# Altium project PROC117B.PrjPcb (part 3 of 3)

## Sheet PROC117B_CAN_LIN_PHY_Interface.SchDoc: CAN_LIN_PHY_INTERFACE
size 431 x 279 mm; Date: Not shown in title block; ApprovedBy: Not shown in title block; CheckedBy: Not shown in title block; Author: Not shown in title block; CompanyName: Not shown in title block; DrawnBy: Mistral; Engineer: Not shown in title block; Organization: Not shown in title block; Address1: Not shown in title block; Address2: Not shown in title block; Address3: Not shown in title block; Address4: Not shown in title block; DocumentNumber: 13; Revision: Use project parameter SCH_Rev; SheetNumber: 13; SheetTotal: 16; PageSetup: Record=PageOptions¦CenterHorizontal=True¦CenterVertical=True¦PrintScale=1.00¦XCorrection=1.00¦YCorrection=1.00¦PrintKind=0¦BorderSize=5000000¦LeftOffset=0¦BottomOffset=0¦Orientation=2¦PaperLength=1000¦PaperWidth=1000¦Scale=100¦PaperSource=15¦PrintQuality=600¦MediaType=1¦DitherType=10¦PaperKind=Letter¦PrintScaleMode=1
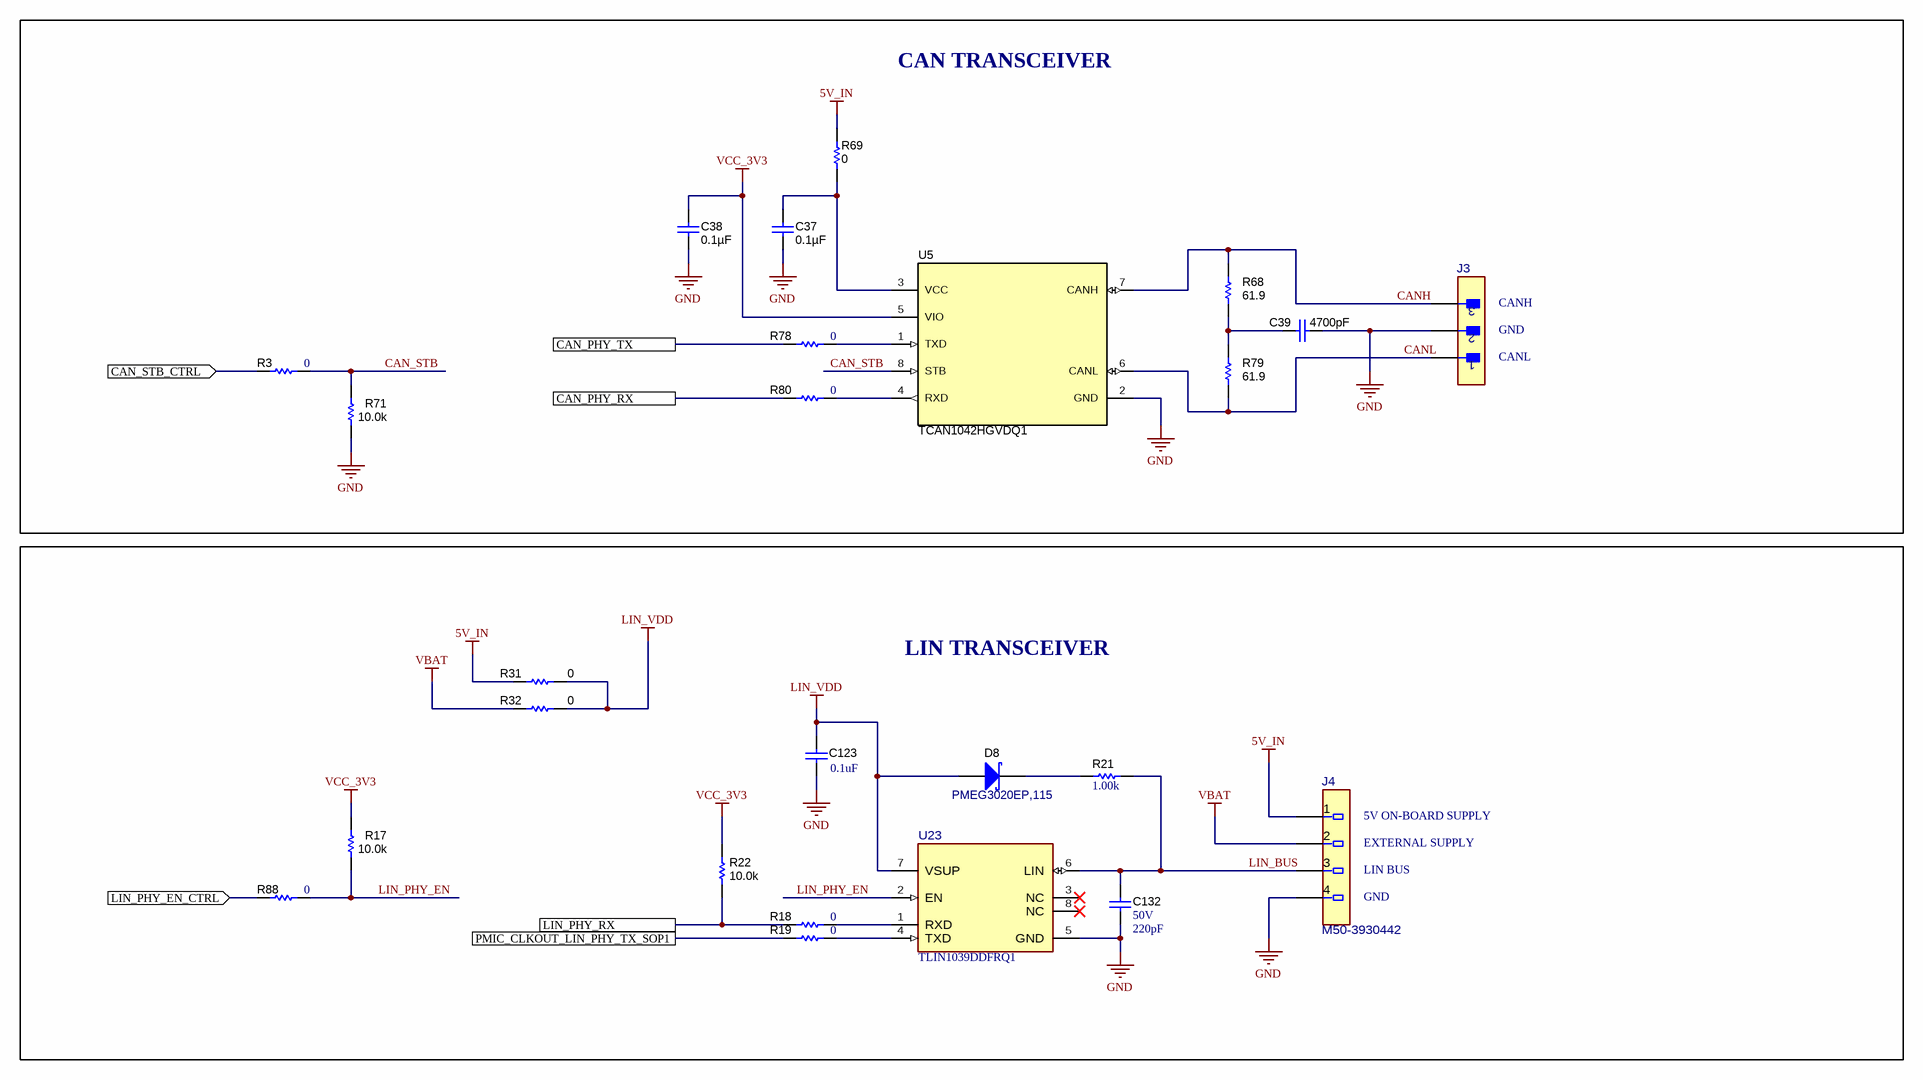
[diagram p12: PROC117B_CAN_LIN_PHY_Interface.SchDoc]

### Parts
C37  ValueDisplayed: 0.1µF  [0402L]  (hidden comment: C0402C104K8RACTU)
C38  ValueDisplayed: 0.1µF  [0402L]  (hidden comment: C0402C104K8RACTU)
C39  ValueDisplayed: 4700pF  [0402L]  (hidden comment: GCM155R71H472KA37D)
C123  ValueDisplayed: 0.1uF  [0402]  (hidden comment: GCM155R71H104KE02D)
C132  VDC_V: 50V  ValueDisplayed: 220pF  [0402]  (hidden comment: 885012005063)
D8  PMEG3020EP,115  [SOD-128]
J3  M50-3930342  [FP-M50-3930342_HDR3-MFG]  (value not drawn)
J4  M50-3930442  [FP-M50-3930442_HDR4-Recommended_Land_Pattern]
R3  ValueDisplayed: 0  [0402]  (hidden comment: ERJ-2GE0R00X)
R17  ValueDisplayed: 10.0k  [0402L]  (hidden comment: CRCW040210K0FKED)
R18  ValueDisplayed: 0  [0402]  (hidden comment: ERJ-2GE0R00X)
R19  ValueDisplayed: 0  [0402]  (hidden comment: ERJ-2GE0R00X)
R21  ValueDisplayed: 1.00k  [0402]  (hidden comment: CRCW04021K00FKED)
R22  ValueDisplayed: 10.0k  [0402L]  (hidden comment: CRCW040210K0FKED)
R31  ValueDisplayed: 0  [0603]  (hidden comment: MCT06030Z0000ZP500)
R32  ValueDisplayed: 0  [0603]  (hidden comment: MCT06030Z0000ZP500)
R68  ValueDisplayed: 61.9  [0402L]  (hidden comment: CRCW040261R9FKED)
R69  ValueDisplayed: 0  [0201_Silk]  (hidden comment: CRCW02010000Z0ED)
R71  ValueDisplayed: 10.0k  [0402L]  (hidden comment: CRCW040210K0FKED)
R78  ValueDisplayed: 0  [0402]  (hidden comment: ERJ-2GE0R00X)
R79  ValueDisplayed: 61.9  [0402L]  (hidden comment: CRCW040261R9FKED)
R80  ValueDisplayed: 0  [0402]  (hidden comment: ERJ-2GE0R00X)
R88  ValueDisplayed: 0  [0402]  (hidden comment: ERJ-2GE0R00X)
U5  TCAN1042HGVDQ1  [D0008A_L]
U23  TLIN1039DDFRQ1  [DDF0008A-MFG]

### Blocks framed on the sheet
CAN TRANSCEIVER: C37-C39 J3 R3 R68 R69 R71 R78-R80 U5
LIN TRANSCEIVER: C123 C132 D8 J4 R17-R19 R21 R22 R31 R32 R88 U23

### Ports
CAN_PHY_RX, CAN_PHY_TX, CAN_STB_CTRL (in), LIN_PHY_EN_CTRL (in), LIN_PHY_RX, PMIC_CLKOUT_LIN_PHY_TX_SOP1

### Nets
5V_IN: J4.1 R31.1 R69.2
GND: C37.1 C38.1 C39.1 C123.2 C132.2 J3.2 J4.4 R71.1 U5.2(GND) U23.5(GND)
LIN_VDD: C123.1 D8.2(A) R31.2 R32.2 U23.7(VSUP)
VBAT: J4.2 R32.1
VCC_3V3: C38.2 R17.2 R22.2 U5.5(VIO)
CAN_PHY_RX: R80.1 ; port CAN_PHY_RX
CAN_PHY_TX: R78.1 ; port CAN_PHY_TX
CAN_STB: R3.2 R71.2 U5.8(STB)
CAN_STB_CTRL: R3.1 ; port CAN_STB_CTRL
CANH: J3.3 R68.2 U5.7(CANH)
CANL: J3.1 R79.1 U5.6(CANL)
LIN_BUS: C132.1 J4.3 R21.1 U23.6(LIN)
LIN_PHY_EN: R17.1 R88.2 U23.2(EN)
LIN_PHY_EN_CTRL: R88.1 ; port LIN_PHY_EN_CTRL
LIN_PHY_RX: R18.1 R22.1 ; port LIN_PHY_RX
PMIC_CLKOUT_LIN_PHY_TX_SOP1: R19.1 ; port PMIC_CLKOUT_LIN_PHY_TX_SOP1
NetC37_2: C37.2 R69.1 U5.3(VCC)
NetC39_2: C39.2 R68.1 R79.2
NetD8_1: D8.1(K) R21.2
NetR18_2: R18.2 U23.1(RXD)
NetR19_2: R19.2 U23.4(TXD)
NetR78_2: R78.2 U5.1(TXD)
NetR80_2: R80.2 U5.4(RXD)

Not connected (* = marked no-connect by the designer): U23 3(NC)* 8(NC)*

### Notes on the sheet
- (near J3) CANH
- (near J3) GND
- (near J3) CANL
- (near J4) EXTERNAL SUPPLY
- (near J4) 5V ON-BOARD SUPPLY
- (near J4) GND
- (near J4) LIN BUS

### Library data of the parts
C37 C38 = CMP-0078241-1: CAP, CERM, 0.1 µF, 10 V,+/- 10%, X7R, 0402; Manufacturer: Kemet; TaMin_C: -55°C; Polarized: N; SizeAreaWB_mm2: 3; U/M: EA; Value: 0.1uF; TaMax_C: 125°C; SizeZ_mm: 0.6; SizeX_mm: 1; SizeY_mm: 0.5; Cap_Case: 0402; Value2: 10V; CompType: Capacitor; Cap_F: 100nF; AEC Category: Q200
C39 = CMP-0006361-2: CAP, CERM, 4700 pF, 50 V, +/- 10%, X7R, AEC-Q200 Grade 1, 0402; Manufacturer: MuRata; TaMin_C: -55°C; Polarized: N; SizeAreaWB_mm2: 3; Value1: Unknown; U/M: EA; Value: 4700pF; TaMax_C: 125°C; SizeZ_mm: 0.6; SizeX_mm: 1; SizeY_mm: 0.5; Cap_Case: 0402; Value2: 50V; AEC Qualified: Y; Cap_F: 4.7nF; AEC Category: Q200
C123 = CMP-0006356-2: CAP, CERM, 0.1 uF, 50 V, +/- 10%, X7R, AEC-Q200 Grade 1, 0402; Manufacturer: MuRata; TaMin_C: -55°C; Polarized: N; SizeAreaWB_mm2: 3; Value1: Unknown; U/M: EA; Value: 0.1uF; TaMax_C: 125°C; SizeZ_mm: 0.6; SizeX_mm: 1; SizeY_mm: 0.5; Value2: 50V; AEC Qualified: Y; Cap_F: 100nF; AEC Category: Q200
C132 = CMP-0006218-2: CAP, CERM, 220 pF, 50 V, +/- 5%, C0G/NP0, 0402; Manufacturer: Wurth Elektronik; TaMin_C: -55°C; Polarized: N; SizeAreaWB_mm2: 3; Value1: Unknown; U/M: EA; Value: 220pF; TaMax_C: 125°C; SizeZ_mm: 0.6; SizeX_mm: 1; SizeY_mm: 0.5; AEC Category: Q200
D8 = CMP-0078758-2: Diode, Schottky, 30 V, 2 A, AEC-Q101, SOD-128; Manufacturer: Nexperia; Value2: 0.36V; SizeAreaWB_mm2: 19.6; Io_A: 2A; Value: 30V; AEC Qualified: Y; TJmax_C: 150°C; SizeX_mm: 4.6; AEC Category: Q101; SizeY_mm: 2.5; SizeArea_mm2: 11.5; Vf_V: 3.6dV; SizeZ_mm: 1.1
J3 = CMP-0087785-1: CONN HEADER R/A 3POS 1.27MM; Manufacturer: Harwin; Row_Count: 1; Current_A: 1A; ContactFinish: Gold,Nickel
J4 = CMP-0087187-1: CONN HDR 1.27MM R/A AU 4POS; Manufacturer: Harwin Inc.; ContactFinish: Gold; Current_A: 1A; Row_Count: 1
R3 R18 R19 R78 R80 R88 = CMP-0026992-3: RES, 0, 5%, 0.1 W, AEC-Q200 Grade 0, 0402; Manufacturer: Panasonic; Power_W: 100mW; TempCo: 600 ppm/C; Value_Code: 0000; Value: 0; EIA_Code: E24; SizeX_mm: 1; SizeY_mm: 0.5; SizeZ_mm: 0.6; Value2: 0.1W; CompType: Resistor; AEC Qualified: Y; VDC_V: 50V; AEC Category: Q200; SizeAreaWB_mm2: 3; INSTALLATION: DNP
R17 R22 R71 = CMP-0025958-3: RES, 10.0 k, 1%, 0.063 W, AEC-Q200 Grade 0, 0402; Manufacturer: Vishay-Dale; Power_W: 63mW; TempCo: 100 ppm/C; Value_Code: 10k0; Value: 10.0k; EIA_Code: E96; Res_ohm: 10k; SizeX_mm: 1; SizeY_mm: 0.5; SizeZ_mm: 0.6; Value2: 0.063W; AEC Qualified: Y; VDC_V: 50V; AEC Category: Q200; AEC Grade: 0
R21 = CMP-0026071-3: RES, 1.00 k, 1%, 0.063 W, AEC-Q200 Grade 0, 0402; Manufacturer: Vishay-Dale; Power_W: 63mW; TempCo: 100 ppm/C; Value_Code: 1k00; Value: 1.00k; EIA_Code: E96; Res_ohm: 1k; SizeX_mm: 1; SizeY_mm: 0.5; SizeZ_mm: 0.6; Value2: 0.063W; AEC Qualified: Y; VDC_V: 50V; AEC Category: Q200; AEC Grade: 0
R31 R32 = CMP-0025884-3: RES, 0, 5%, 0.125 W, 0603; Manufacturer: Vishay/Beyschlag; Power_W: 125mW; TempCo: ppm/C; Value_Code: 0000; U/M: EA; Value: 0; EIA_Code: E24; SizeX_mm: 1.6; SizeY_mm: 0.8; SizeZ_mm: 1; Value2: 0.125W; SizeArea_mm2: 1.28; CompType: Resistor; AEC Qualified: N; AEC Category: Q200; INSTALATION: DNP
R68 R79 = CMP-0026491-2: RES, 61.9, 1%, 0.063 W, AEC-Q200 Grade 0, 0402; Manufacturer: Vishay-Dale; Power_W: 63mW; TempCo: 100 ppm/C; Value_Code: 61R9; Value: 61.9; EIA_Code: E96; SizeX_mm: 1; SizeY_mm: 0.5; SizeZ_mm: 0.6; Value2: 0.063W; AEC Qualified: Y; VDC_V: 50V; AEC Category: Q200; AEC Grade: 0
R69 = CMP-0027008-4: RES, 0, 5%, 0.05 W, 0201; Manufacturer: Vishay-Dale; Power_W: 50mW; TempCo: ppm/C; Value_Code: 0000; Value: 0; EIA_Code: E24; SizeX_mm: 0.6; SizeY_mm: 0.3; SizeZ_mm: 0.26; Value2: 0.05W; SizeArea_mm2: 0.18; AEC Qualified: N; AEC Category: Q200
U5 = CMP-0075992-1: Automotive Fault Protected CAN Transceiver With Flexible Data-Rate, D0008A (SOIC-8); Manufacturer: Texas Instruments; Alternate PartNumber: TCAN1042HGVDRQ1; SizeAreaWB_mm2: 56.58; SizeArea_mm2: 30.38; SizeZ_mm: 1.75; SizeY_mm: 6.2; U/M: EA; CompType: IC; SizeX_mm: 4.9
U23 = CMP-0090433-1: Local Interconnect Network (LIN) Transceiver with Dominant State Timeout; Manufacturer: Texas Instruments; Max Supply Voltage: 36V; SizeZ_mm: 1.1mm; Min Supply Voltage: 4.5V; Standoff Height: 0mm; Nominal Supply Current: 0.3-1.2mA; AEC Grade: Grade 0; TJmax_C: +150°C; Interface: UART,LIN,SCI; AEC Qualified: Yes

## Sheet PROC117B_DCA1000_Connector_Reset.SchDoc: DCA1000_CONN_RESET
size 431 x 279 mm; Date: Not shown in title block; ApprovedBy: Not shown in title block; CheckedBy: Not shown in title block; Author: Not shown in title block; CompanyName: Not shown in title block; DrawnBy: Mistral; Engineer: Not shown in title block; Organization: Not shown in title block; Address1: Not shown in title block; Address2: Not shown in title block; Address3: Not shown in title block; Address4: Not shown in title block; DocumentNumber: 14; Revision: Use project parameter SCH_Rev; SheetNumber: 14; SheetTotal: 16; PageSetup: Record=PageOptions¦CenterHorizontal=True¦CenterVertical=True¦PrintScale=1.00¦XCorrection=1.00¦YCorrection=1.00¦PrintKind=0¦BorderSize=5000000¦LeftOffset=0¦BottomOffset=0¦Orientation=2¦PaperLength=1000¦PaperWidth=1000¦Scale=100¦PaperSource=15¦PrintQuality=600¦MediaType=1¦DitherType=10¦PaperKind=Letter¦PrintScaleMode=1
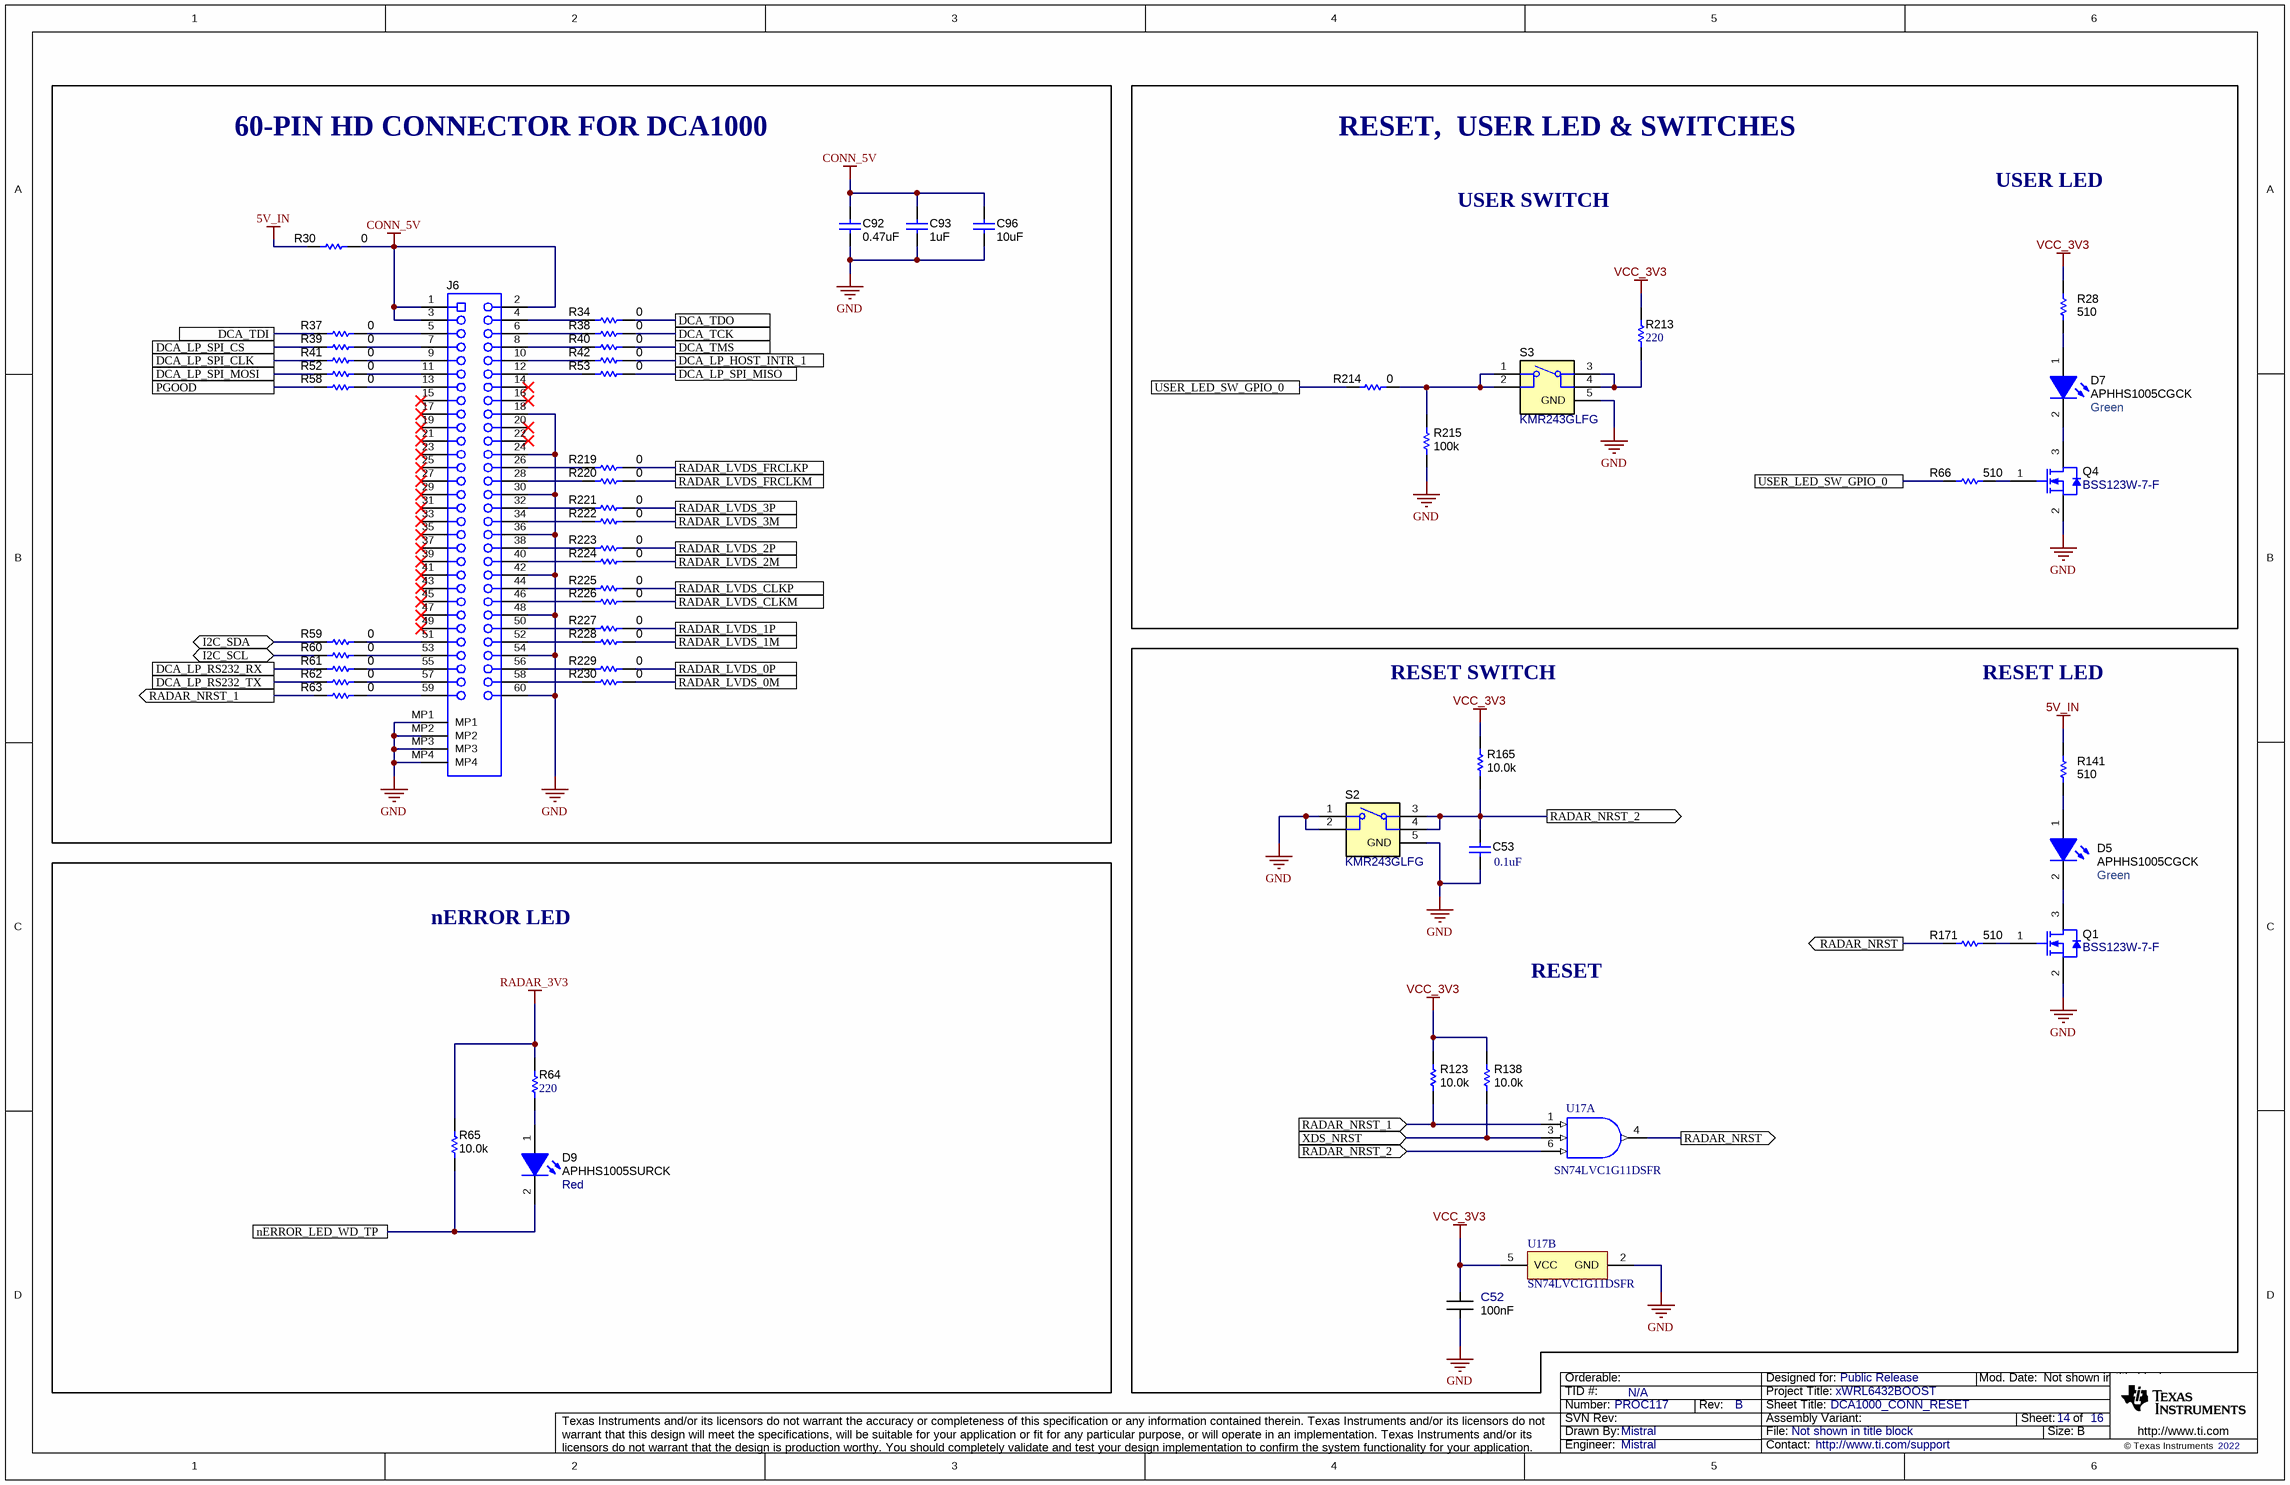
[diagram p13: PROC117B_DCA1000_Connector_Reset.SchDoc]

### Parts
C52  value 100nF  [FP-GRM033R6YA104KE14D_0201 (0603 Metric)-IPC_C]  (hidden comment: GRM033R6YA104KE14D)
C53  ValueDisplayed: 0.1uF  [0402]  (hidden comment: GCM155R71H104KE02D)
C92  ValueDisplayed: 0.47uF  [0402L]  (hidden comment: GCM155C71A474KE36D)
C93  ValueDisplayed: 1uF  [0402L]  (hidden comment: GRT155C81A105KE01D)
C96  ValueDisplayed: 10uF  [0603S]  (hidden comment: GRT188R61A106KE13D)
D5  APHHS1005CGCK  Color: Green  [APHHS1005_Green]
D7  APHHS1005CGCK  Color: Green  [APHHS1005_Green]
D9  APHHS1005SURCK  value Red  [APHHS1005_Red]
J6  QSH-030-01-L-D-A  [Samtec_QSH-030-01-X-D-A]  (value not drawn)
Q1  BSS123W-7-F  [SOT-323]
Q4  BSS123W-7-F  [SOT-323]
R28  value 510  [0201L]  (hidden comment: RC0201JR-07510RL)
R30  ValueDisplayed: 0  [0603]  (hidden comment: MCT06030Z0000ZP500)
R34  ValueDisplayed: 0  [0201_Silk]  (hidden comment: CRCW02010000Z0ED)
R37  ValueDisplayed: 0  [0201_Silk]  (hidden comment: CRCW02010000Z0ED)
R38  ValueDisplayed: 0  [0201_Silk]  (hidden comment: CRCW02010000Z0ED)
R39  ValueDisplayed: 0  [0201_Silk]  (hidden comment: CRCW02010000Z0ED)
R40  ValueDisplayed: 0  [0201_Silk]  (hidden comment: CRCW02010000Z0ED)
R41  ValueDisplayed: 0  [0201_Silk]  (hidden comment: CRCW02010000Z0ED)
R42  ValueDisplayed: 0  [0201_Silk]  (hidden comment: CRCW02010000Z0ED)
R52  ValueDisplayed: 0  [0201_Silk]  (hidden comment: CRCW02010000Z0ED)
R53  ValueDisplayed: 0  [0201_Silk]  (hidden comment: CRCW02010000Z0ED)
R58  ValueDisplayed: 0  [0201_Silk]  (hidden comment: CRCW02010000Z0ED)
R59  ValueDisplayed: 0  [0201_Silk]  (hidden comment: CRCW02010000Z0ED)
R60  ValueDisplayed: 0  [0201_Silk]  (hidden comment: CRCW02010000Z0ED)
R61  ValueDisplayed: 0  [0201_Silk]  (hidden comment: CRCW02010000Z0ED)
R62  ValueDisplayed: 0  [0201_Silk]  (hidden comment: CRCW02010000Z0ED)
R63  ValueDisplayed: 0  [0201_Silk]  (hidden comment: CRCW02010000Z0ED)
R64  ValueDisplayed: 220  [0201]  (hidden comment: RC0201JR-07220RL)
R65  ValueDisplayed: 10.0k  [0402L]  (hidden comment: CRCW040210K0FKED)
R66  value 510  [0201L]  (hidden comment: RC0201JR-07510RL)
R123  ValueDisplayed: 10.0k  [0402L]  (hidden comment: CRCW040210K0FKED)
R138  ValueDisplayed: 10.0k  [0402L]  (hidden comment: CRCW040210K0FKED)
R141  value 510  [0201L]  (hidden comment: RC0201JR-07510RL)
R165  ValueDisplayed: 10.0k  [0402L]  (hidden comment: CRCW040210K0FKED)
R171  value 510  [0201L]  (hidden comment: RC0201JR-07510RL)
R213  ValueDisplayed: 220  [0201]  (hidden comment: RC0201JR-07220RL)
R214  Res_ohm: 0  [FP-RC0201JR-070RL_0201 (0603 Metric)-IPC_C]  (hidden comment: RC0201JR-070RL)
R215  value 100k  [0201L]  (hidden comment: CRCW0201100KFKED)
R219  ValueDisplayed: 0  [0201_Silk]  (hidden comment: CRCW02010000Z0ED)
R220  ValueDisplayed: 0  [0201_Silk]  (hidden comment: CRCW02010000Z0ED)
R221  ValueDisplayed: 0  [0201_Silk]  (hidden comment: CRCW02010000Z0ED)
R222  ValueDisplayed: 0  [0201_Silk]  (hidden comment: CRCW02010000Z0ED)
R223  ValueDisplayed: 0  [0201_Silk]  (hidden comment: CRCW02010000Z0ED)
R224  ValueDisplayed: 0  [0201_Silk]  (hidden comment: CRCW02010000Z0ED)
R225  ValueDisplayed: 0  [0201_Silk]  (hidden comment: CRCW02010000Z0ED)
R226  ValueDisplayed: 0  [0201_Silk]  (hidden comment: CRCW02010000Z0ED)
R227  ValueDisplayed: 0  [0201_Silk]  (hidden comment: CRCW02010000Z0ED)
R228  ValueDisplayed: 0  [0201_Silk]  (hidden comment: CRCW02010000Z0ED)
R229  ValueDisplayed: 0  [0201_Silk]  (hidden comment: CRCW02010000Z0ED)
R230  ValueDisplayed: 0  [0201_Silk]  (hidden comment: CRCW02010000Z0ED)
S2  KMR243GLFG  [SW_KMR243GLFG]
S3  KMR243GLFG  [SW_KMR243GLFG]
U17  SN74LVC1G11DSFR  [DSF0006A]  (parts A,B of 2)

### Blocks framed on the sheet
60-PIN HD CONNECTOR FOR DCA1000: C92 C93 C96 J6 R30 R34 R37-R42 R52 R53 R58-R63 R219-R230
RESET,  USER LED & SWITCHES: D7 Q4 R28 R66 R213-R215 S3
nERROR LED: D9 R64 R65

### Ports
DCA_LP_HOST_INTR_1, DCA_LP_RS232_RX, DCA_LP_RS232_TX, DCA_LP_SPI_CLK, DCA_LP_SPI_CS, DCA_LP_SPI_MISO, DCA_LP_SPI_MOSI, DCA_TCK, DCA_TDI, DCA_TDO, DCA_TMS, I2C_SCL (bidir), I2C_SDA (bidir), nERROR_LED_WD_TP, PGOOD, RADAR_LVDS_0M, RADAR_LVDS_0P, RADAR_LVDS_1M, RADAR_LVDS_1P, RADAR_LVDS_2M, RADAR_LVDS_2P, RADAR_LVDS_3M, RADAR_LVDS_3P, RADAR_LVDS_CLKM, RADAR_LVDS_CLKP, RADAR_LVDS_FRCLKM, RADAR_LVDS_FRCLKP, RADAR_NRST (out), RADAR_NRST_1 (in), RADAR_NRST_1 (out), RADAR_NRST_2 (in), RADAR_NRST_2 (out), USER_LED_SW_GPIO_0, XDS_NRST (in)

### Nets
5V_IN: R30.1 R141.1
CONN_5V: C92.1 C93.1 C96.2 J6.1 J6.2 J6.3 R30.2
GND: C52.1 C53.2 C92.2 C93.2 C96.1 J6.18 J6.24 J6.30 J6.36 J6.42 J6.48 J6.54 J6.60 J6.MP1 J6.MP2 J6.MP3 J6.MP4 Q1.2(S) Q4.2(S) R215.2 S2.1 S2.2 S2.5(GND) S3.5(GND) U17.2(GND)
RADAR_3V3: R64.2 R65.1
VCC_3V3: C52.2 R28.1 R123.2 R138.2 R165.2 R213.2 U17.5(VCC)
DCA_LP_HOST_INTR_1: R42.2 ; port DCA_LP_HOST_INTR_1
DCA_LP_RS232_RX: R61.1 ; port DCA_LP_RS232_RX
DCA_LP_RS232_TX: R62.1 ; port DCA_LP_RS232_TX
DCA_LP_SPI_CLK: R41.1 ; port DCA_LP_SPI_CLK
DCA_LP_SPI_CS: R39.1 ; port DCA_LP_SPI_CS
DCA_LP_SPI_MISO: R53.2 ; port DCA_LP_SPI_MISO
DCA_LP_SPI_MOSI: R52.1 ; port DCA_LP_SPI_MOSI
DCA_TCK: R38.2 ; port DCA_TCK
DCA_TDI: R37.1 ; port DCA_TDI
DCA_TDO: R34.2 ; port DCA_TDO
DCA_TMS: R40.2 ; port DCA_TMS
I2C_SCL: R60.1 ; port I2C_SCL
I2C_SDA: R59.1 ; port I2C_SDA
nERROR_LED_WD_TP: D9.2(K) R65.2 ; port nERROR_LED_WD_TP
PGOOD: R58.1 ; port PGOOD
RADAR_LVDS_0M: R230.2 ; port RADAR_LVDS_0M
RADAR_LVDS_0P: R229.2 ; port RADAR_LVDS_0P
RADAR_LVDS_1M: R228.2 ; port RADAR_LVDS_1M
RADAR_LVDS_1P: R227.2 ; port RADAR_LVDS_1P
RADAR_LVDS_2M: R224.2 ; port RADAR_LVDS_2M
RADAR_LVDS_2P: R223.2 ; port RADAR_LVDS_2P
RADAR_LVDS_3M: R222.2 ; port RADAR_LVDS_3M
RADAR_LVDS_3P: R221.2 ; port RADAR_LVDS_3P
RADAR_LVDS_CLKM: R226.2 ; port RADAR_LVDS_CLKM
RADAR_LVDS_CLKP: R225.2 ; port RADAR_LVDS_CLKP
RADAR_LVDS_FRCLKM: R220.2 ; port RADAR_LVDS_FRCLKM
RADAR_LVDS_FRCLKP: R219.2 ; port RADAR_LVDS_FRCLKP
RADAR_NRST: R171.1 U17.4(Y) ; port RADAR_NRST
RADAR_NRST_1: R63.1 R123.1 U17.1(A) ; port RADAR_NRST_1
RADAR_NRST_2: C53.1 R165.1 S2.3 S2.4 U17.6(C) ; port RADAR_NRST_2
USER_LED_SW_GPIO_0: R66.1 R214.2 ; port USER_LED_SW_GPIO_0
XDS_NRST: R138.1 U17.3(B) ; port XDS_NRST
NetD5_1: D5.1(A) R141.2
NetD5_2: D5.2(K) Q1.3(D)
NetD7_1: D7.1(A) R28.2
NetD7_2: D7.2(K) Q4.3(D)
NetD9_1: D9.1(A) R64.1
NetJ6_4: J6.4 R34.1
NetJ6_5: J6.5 R37.2
NetJ6_6: J6.6 R38.1
NetJ6_7: J6.7 R39.2
NetJ6_8: J6.8 R40.1
NetJ6_9: J6.9 R41.2
NetJ6_10: J6.10 R42.1
NetJ6_11: J6.11 R52.2
NetJ6_12: J6.12 R53.1
NetJ6_13: J6.13 R58.2
NetJ6_26: J6.26 R219.1
NetJ6_28: J6.28 R220.1
NetJ6_32: J6.32 R221.1
NetJ6_34: J6.34 R222.1
NetJ6_38: J6.38 R223.1
NetJ6_40: J6.40 R224.1
NetJ6_44: J6.44 R225.1
NetJ6_46: J6.46 R226.1
NetJ6_50: J6.50 R227.1
NetJ6_51: J6.51 R59.2
NetJ6_52: J6.52 R228.1
NetJ6_53: J6.53 R60.2
NetJ6_55: J6.55 R61.2
NetJ6_56: J6.56 R229.1
NetJ6_57: J6.57 R62.2
NetJ6_58: J6.58 R230.1
NetJ6_59: J6.59 R63.2
NetQ1_1: Q1.1(G) R171.2
NetQ4_1: Q4.1(G) R66.2
NetR213_1: R213.1 S3.3 S3.4
NetR214_1: R214.1 R215.1 S3.1 S3.2

Not connected (* = marked no-connect by the designer): J6 14* 15* 16* 17* 19* 20* 21* 22* 23* 25* 27* 29* 31* 33* 35* 37* 39* 41* 43* 45* 47* 49*

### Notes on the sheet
- USER SWITCH
- USER LED
- RESET SWITCH
- RESET LED
- RESET

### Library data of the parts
C52 = CMP-0086440-1: Cap Ceramic 0.1uF 35V X5R 10% Pad SMD 0201 85C T/R; Manufacturer: Murata Electronics North America; AEC Qualified: No; SizeZ_mm: 0.33mm; Symbol Name: SYM-GRM033R6YA104KE14D; TempCo: 15%
C53 = CMP-0006356-2: as C123 on sheet PROC117B_CAN_LIN_PHY_Interface
C92 = CMP-0064967-2: CAP, CERM, 0.47 uF, 10 V,+/- 10%, X7S, 0402; Manufacturer: MuRata; Polarized: N; Value: 0.47uF; U/M: EA; Cap_F: 470nF; Value1: Unknown; VDC_V: 10V; TaMin_C: -55°C; TaMax_C: 125°C; Cap_Case: 0402; SizeArea_mm2: 0.5; SizeAreaWB_mm2: 3; SizeX_mm: 1; SizeZ_mm: 0.6; AEC Category: Q200
C93 = CMP-0006272-2: CAP, CERM, 1 uF, 10 V, +/- 10%, X6S, 0402; Manufacturer: TDK; Polarized: N; Value: 1uF; U/M: EA; Cap_F: 1µF; Value1: Unknown; VDC_V: 16V; TempCo: X5R; TaMin_C: -55°C; TaMax_C: 85°C; Cap_Case: 0402; SizeArea_mm2: 0.5; SizeAreaWB_mm2: 3; SizeX_mm: 1; SizeZ_mm: 0.6; AEC Category: Q200
C96 = CMP-0007497-5: CAP, CERM, 10 uF, 10 V, +/- 10%, X5R, 0603; Manufacturer: MuRata; Polarized: N; Value: 10uF; U/M: EA; Cap_F: 10µF; Tolerance_%: 20%; Value1: Unknown; VDC_V: 10V; TempCo: X7R; TaMin_C: -55°C; TaMax_C: 125°C; Cap_Case: 0603; SizeArea_mm2: 1.28; SizeAreaWB_mm2: 4.68; SizeX_mm: 1.6; SizeY_mm: 0.8; SizeZ_mm: 1; AEC Category: Q200
D5 D7 = CMP-0067682-2: LED, Green, SMD; Manufacturer: Kingbright; Angle: 120.0; Power_TotalModule: 75mW; SizeZ_mm: 0.6; Vf_V: 2.1V; Vr_V: 5V; Io_A: 20mA; Ir_A: 10µA; SizeArea_mm2: 0.5; SizeAreaWB_mm2: 3.0; SizeX_mm: 1.0; Tjmax_C: 85°C; Value1: 0.075W
D9 = CMP-0067681-2: LED, Red, SMD; Manufacturer: Kingbright; Vf_V: 1.95V; SizeAreaWB_mm2: 3.0; Tjmax_C: 85°C; SizeX_mm: 1.0; Io_A: 20mA; SizeArea_mm2: 0.5; Vr_V: 5V; Value1: 0.075W; SizeZ_mm: 0.6; Angle: 120.0; Ir_A: 10µA; Power_TotalModule: 75mW
J6 = CMP-0075524-1: Receptacle, 0.5 mm, 30x2, Gold, TH; Manufacturer: Samtec; Pitch_mm: 0.5; Gender: Female; Green_REACh: Passed; CT: False; Shrouded: N; RowSpacing_mm: 5.73; Green_Lifecycle: Active; Row_Count: 2
Q1 Q4 = CMP-0000948-2: MOSFET, N-CH, 100 V, 0.17 A, SOT-323; Alternate Manufacturer: None; Manufacturer: Diodes Inc.; SizeZ_mm: 1.1; ChType: N; Value1: 1; VdsMax_V: 100V; SizeX_mm: 2.2; Vgs_V: 20V; Value: 100V; Rdson45_ohm: 10; SizeArea_mm2: 4.84; AEC Category: Q101; IdsMax_A: 1.7dA; SizeAreaWB_mm2: 10.24; U/M: EA
R28 R66 R141 R171 = CMP-0027137-1: RES, 510, 5%, 0.05 W, 0201; Manufacturer: Yageo America; AEC Category: Q200; AEC Qualified: N; EIA_Code: E24; Power_W: 50mW; SizeArea_mm2: 0.18; SizeX_mm: 0.6; SizeY_mm: 0.3; SizeZ_mm: 0.26; TempCo: 200 ppm/C; U/M: EA; Value2: 0.05W; Value_Code: 510R; VDC_V: 25V
R30 = CMP-0025884-3: as R31 on sheet PROC117B_CAN_LIN_PHY_Interface
R34 R37-R42 R52 R53 R58-R63 R219-R230 = CMP-0027008-4: as R69 on sheet PROC117B_CAN_LIN_PHY_Interface
R64 R213 = CMP-0027072-1: RES, 220, 5%, 0.05 W, 0201; Manufacturer: Yageo America; Power_W: 50mW; TempCo: 200 ppm/C; Value_Code: 220R; U/M: EA; Value: 220; EIA_Code: E24; SizeX_mm: 0.6; SizeY_mm: 0.3; SizeZ_mm: 0.26; Value2: 0.05W; SizeArea_mm2: 0.18; AEC Qualified: N; VDC_V: 25V; AEC Category: Q200
R65 R123 R138 R165 = CMP-0025958-3: as R17 on sheet PROC117B_CAN_LIN_PHY_Interface
R214 = CMP-0086442-2: RES SMD 0 OHM JUMPER 1/20W 0201; Manufacturer: Yageo; AEC Qualified: No; Power_W: 50mW; SizeZ_mm: 0.26mm; TempCo: 200ppm/°C; Tolerance_%: 5%; VDC_V: 25V
R215 = CMP-0027261-3: RES, 100 k, 1%, 0.05 W, 0201; Manufacturer: Vishay-Dale; AEC Category: Q200; AEC Qualified: N; EIA_Code: E96; Power_W: 50mW; SizeArea_mm2: 0.18; SizeX_mm: 0.6; SizeY_mm: 0.3; SizeZ_mm: 0.26; TempCo: 100 ppm/C; Value2: 0.05W; VDC_V: 30V
S2 S3 = CMP-0002325-1: Switch, SPST-NO, Off-Mom, 0.01 A, 32 VDC, SMD; Manufacturer: C&K Components; CurrentRating_mA: 10A; PositionCount: 1; SizeX_mm: 4.6; SizeY_mm: 2.8; SizeZ_mm: 1.9; SizeArea_mm2: 12.88; VDC_V: 32V; SizeAreaWB_mm2: 21.28
U17 = CMP-0051215-4: Single 3-Input Positive-AND Gate, DSF0006A, LARGE T&R; Manufacturer: Texas Instruments; Output Type: CMOS; Bits(#): 1; Input Type: CMOS/TTL; Technology Family: LVC; Schmitt Trigger: No; VCC(Max)(V): 5.5; Gate Type: AND; Rating: Catalog; Output Drive (IOL/IOH)(Max)(mA): 32/-32; ICC @ Nom Voltage(Max)(mA): 0.01; VCC(Min)(V): 1.65; F @ Nom Voltage(Max)(Mhz): 150; Logic: True; Voltage(Nom)(V): 1.8,2.5,3.3,5; tpd @ Nom Voltage(Max)(ns): 20,7.8,6.2,4.6

## Sheet PROC117B_LP_BP_Connector.SchDoc: LP_BP_CONN_HEADER
size 431 x 279 mm; Date: Not shown in title block; ApprovedBy: Not shown in title block; CheckedBy: Not shown in title block; Author: Not shown in title block; CompanyName: Not shown in title block; DrawnBy: Mistral; Engineer: Not shown in title block; Organization: Not shown in title block; Address1: Not shown in title block; Address2: Not shown in title block; Address3: Not shown in title block; Address4: Not shown in title block; DocumentNumber: 15; Revision: Use project parameter SCH_Rev; SheetNumber: 15; SheetTotal: 16; PageSetup: Record=PageOptions¦CenterHorizontal=True¦CenterVertical=True¦PrintScale=1.00¦XCorrection=1.00¦YCorrection=1.00¦PrintKind=0¦BorderSize=5000000¦LeftOffset=0¦BottomOffset=0¦Orientation=2¦PaperLength=1000¦PaperWidth=1000¦Scale=100¦PaperSource=15¦PrintQuality=600¦MediaType=1¦DitherType=10¦PaperKind=Letter¦PrintScaleMode=1
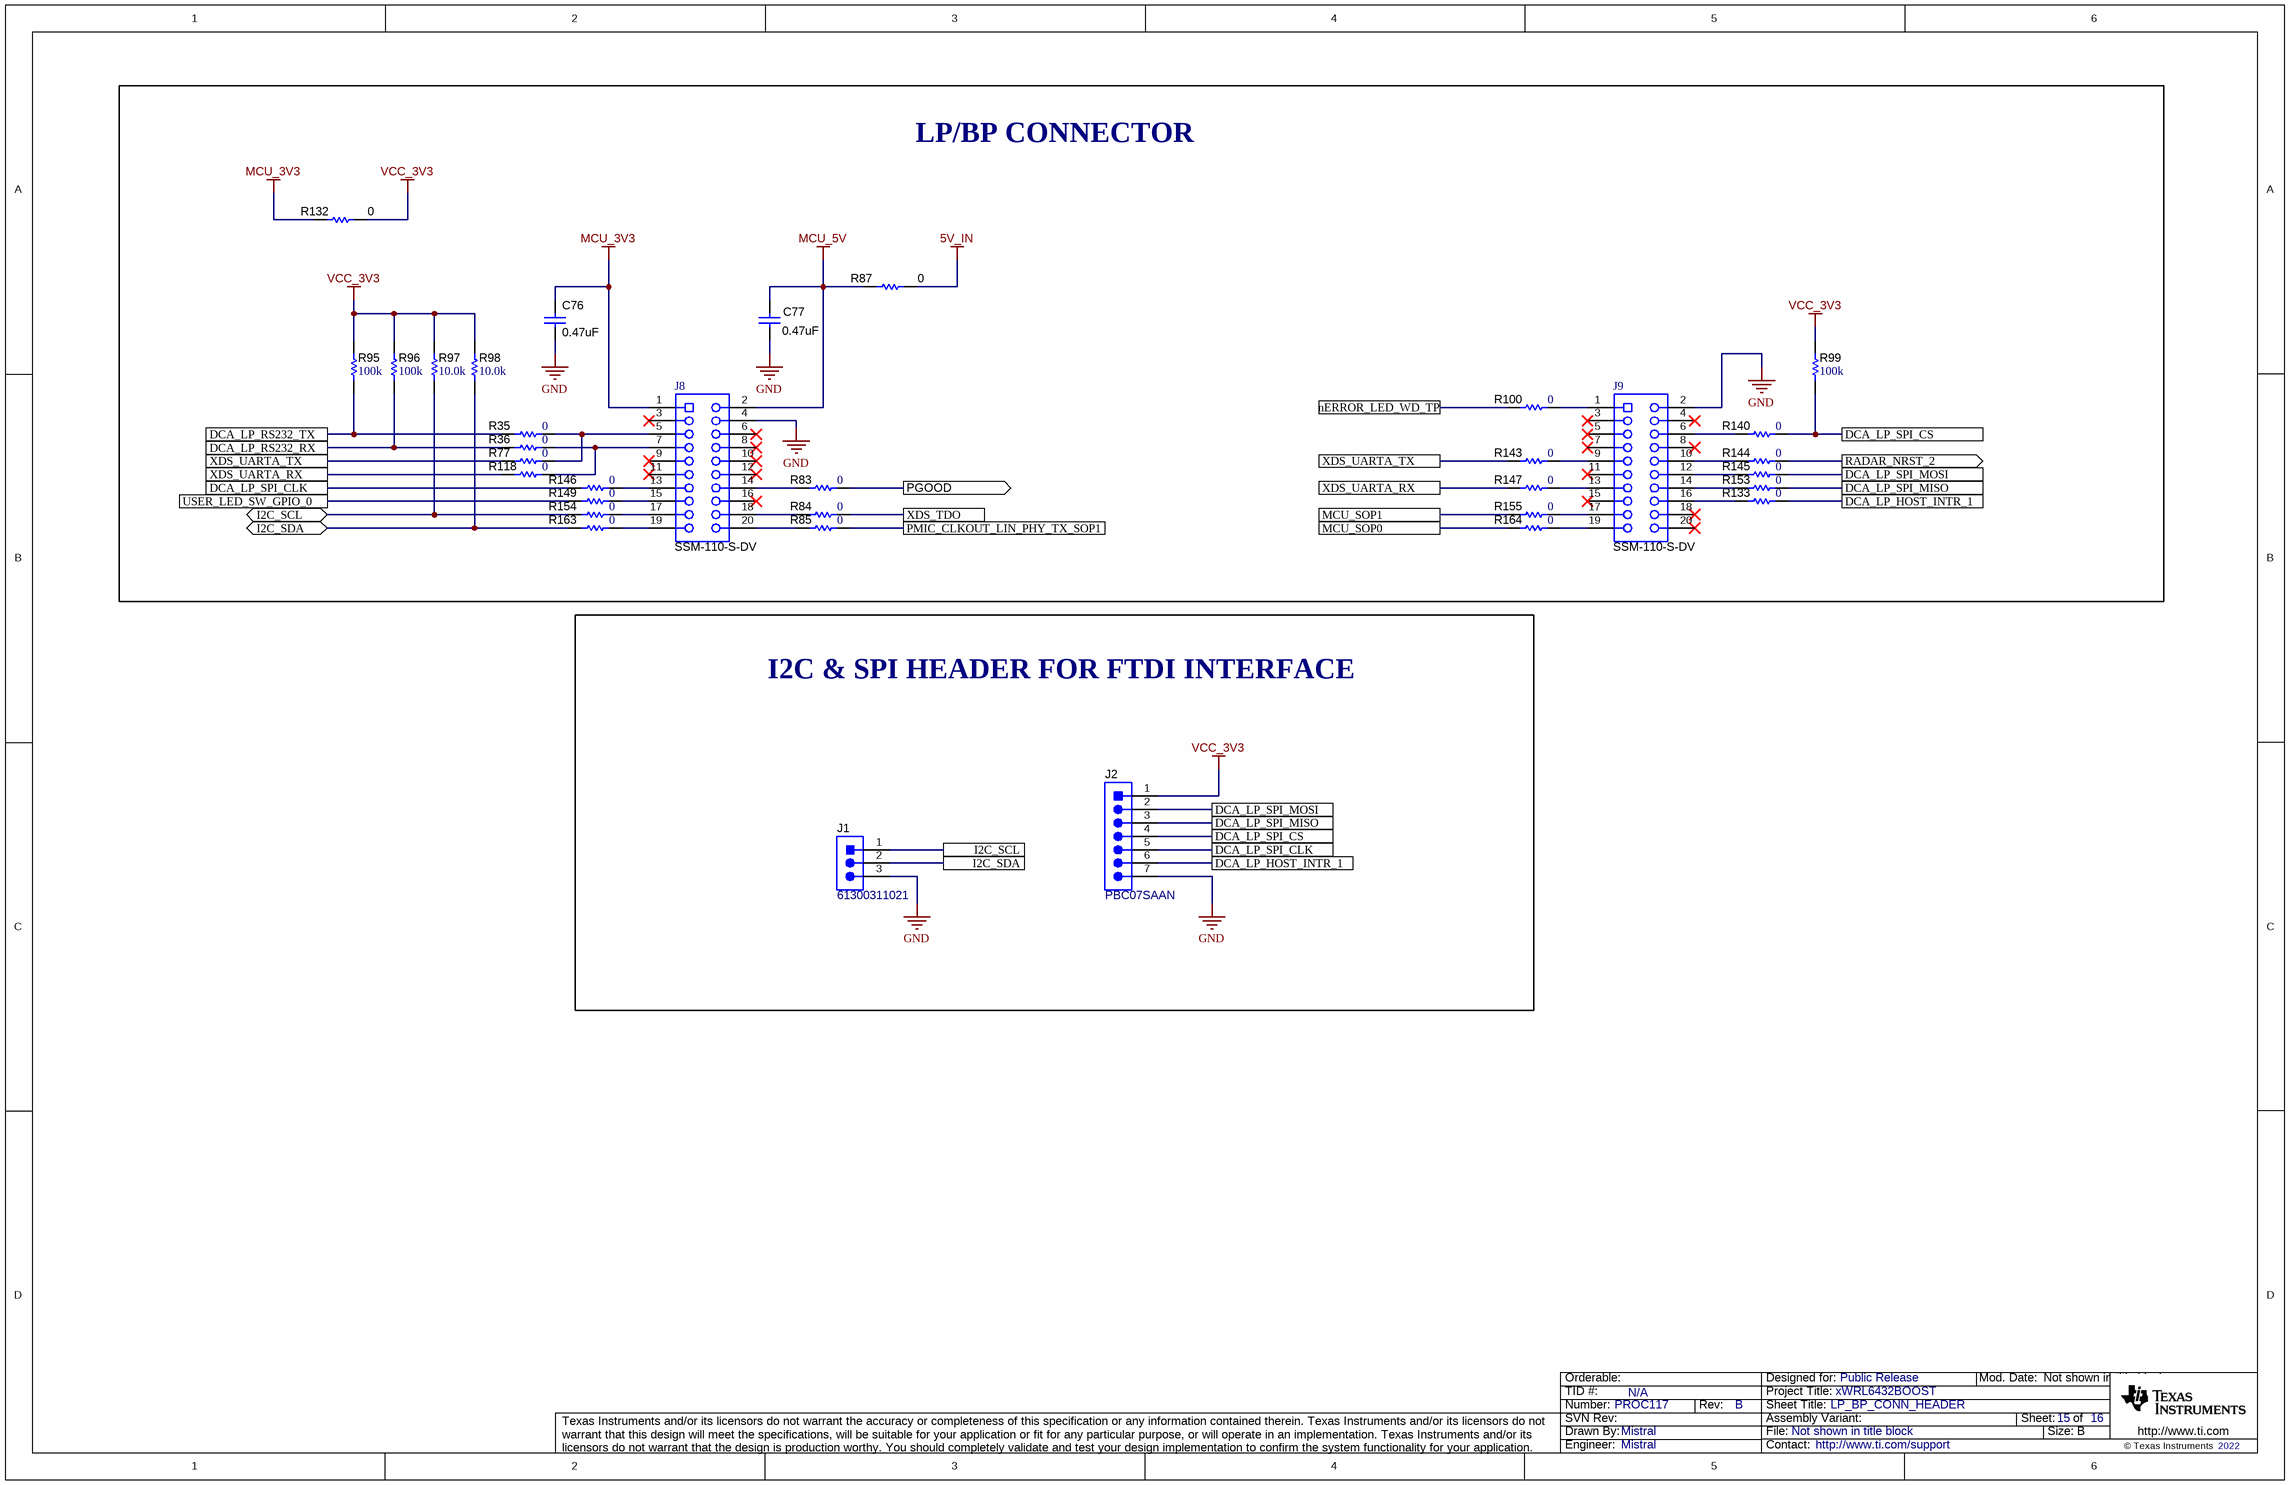
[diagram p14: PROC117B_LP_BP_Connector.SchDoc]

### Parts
C76  ValueDisplayed: 0.47uF  [0402L]  (hidden comment: GCM155C71A474KE36D)
C77  ValueDisplayed: 0.47uF  [0402L]  (hidden comment: GCM155C71A474KE36D)
J1  61300311021  [Wurth_61300311021]
J2  PBC07SAAN  [Sullins_xxC07SAAN]
J8  SSM-110-S-DV  [Samtec_SSM-110-x-DV]
J9  SSM-110-S-DV  [Samtec_SSM-110-x-DV]
R35  ValueDisplayed: 0  [0201_Silk]  (hidden comment: CRCW02010000Z0ED)
R36  ValueDisplayed: 0  [0201_Silk]  (hidden comment: CRCW02010000Z0ED)
R77  ValueDisplayed: 0  [0201_Silk]  (hidden comment: CRCW02010000Z0ED)
R83  ValueDisplayed: 0  [0201_Silk]  (hidden comment: CRCW02010000Z0ED)
R84  ValueDisplayed: 0  [0201_Silk]  (hidden comment: CRCW02010000Z0ED)
R85  ValueDisplayed: 0  [0201_Silk]  (hidden comment: CRCW02010000Z0ED)
R87  ValueDisplayed: 0  [0603]  (hidden comment: MCT06030Z0000ZP500)
R95  ValueDisplayed: 100k  [0402L]  (hidden comment: CRCW0402100KFKED)
R96  ValueDisplayed: 100k  [0402L]  (hidden comment: CRCW0402100KFKED)
R97  ValueDisplayed: 10.0k  [0402L]  (hidden comment: CRCW040210K0FKED)
R98  ValueDisplayed: 10.0k  [0402L]  (hidden comment: CRCW040210K0FKED)
R99  ValueDisplayed: 100k  [0402L]  (hidden comment: CRCW0402100KFKED)
R100  ValueDisplayed: 0  [0201_Silk]  (hidden comment: CRCW02010000Z0ED)
R118  ValueDisplayed: 0  [0201_Silk]  (hidden comment: CRCW02010000Z0ED)
R132  ValueDisplayed: 0  [0603]  (hidden comment: MCT06030Z0000ZP500)
R133  ValueDisplayed: 0  [0201_Silk]  (hidden comment: CRCW02010000Z0ED)
R140  ValueDisplayed: 0  [0201_Silk]  (hidden comment: CRCW02010000Z0ED)
R143  ValueDisplayed: 0  [0201_Silk]  (hidden comment: CRCW02010000Z0ED)
R144  ValueDisplayed: 0  [0201_Silk]  (hidden comment: CRCW02010000Z0ED)
R145  ValueDisplayed: 0  [0201_Silk]  (hidden comment: CRCW02010000Z0ED)
R146  ValueDisplayed: 0  [0201_Silk]  (hidden comment: CRCW02010000Z0ED)
R147  ValueDisplayed: 0  [0201_Silk]  (hidden comment: CRCW02010000Z0ED)
R149  ValueDisplayed: 0  [0201_Silk]  (hidden comment: CRCW02010000Z0ED)
R153  ValueDisplayed: 0  [0201_Silk]  (hidden comment: CRCW02010000Z0ED)
R154  ValueDisplayed: 0  [0201_Silk]  (hidden comment: CRCW02010000Z0ED)
R155  ValueDisplayed: 0  [0201_Silk]  (hidden comment: CRCW02010000Z0ED)
R163  ValueDisplayed: 0  [0201_Silk]  (hidden comment: CRCW02010000Z0ED)
R164  ValueDisplayed: 0  [0201_Silk]  (hidden comment: CRCW02010000Z0ED)

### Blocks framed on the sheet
LP/BP CONNECTOR: C76 C77 J8 J9 R35 R36 R77 R83-R85 R87 R95-R100 R118 R132 R133 R140 R143-R147 R149 R153-R155 R163 R164
I2C & SPI HEADER FOR FTDI INTERFACE: J1 J2

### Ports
DCA_LP_HOST_INTR_1, DCA_LP_RS232_RX, DCA_LP_RS232_TX, DCA_LP_SPI_CLK, DCA_LP_SPI_CS, DCA_LP_SPI_MISO, DCA_LP_SPI_MOSI, I2C_SCL, I2C_SCL (bidir), I2C_SDA, I2C_SDA (bidir), MCU_SOP0, MCU_SOP1, nERROR_LED_WD_TP, PGOOD (out), PMIC_CLKOUT_LIN_PHY_TX_SOP1, RADAR_NRST_2 (out), USER_LED_SW_GPIO_0, XDS_TDO, XDS_UARTA_RX, XDS_UARTA_TX

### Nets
5V_IN: R87.2
GND: C76.2 C77.2 J1.3 J2.7 J8.4 J9.2
MCU_3V3: C76.1 J8.1 R132.1
MCU_5V: C77.1 J8.2 R87.1
VCC_3V3: J2.1 R95.2 R96.2 R97.2 R98.2 R99.2 R132.2
DCA_LP_HOST_INTR_1: J2.6 R133.2 ; port DCA_LP_HOST_INTR_1
DCA_LP_RS232_RX: R36.1 R96.1 ; port DCA_LP_RS232_RX
DCA_LP_RS232_TX: R35.1 R95.1 ; port DCA_LP_RS232_TX
DCA_LP_SPI_CLK: J2.5 R146.1 ; port DCA_LP_SPI_CLK
DCA_LP_SPI_CS: J2.4 R99.1 R140.2 ; port DCA_LP_SPI_CS
DCA_LP_SPI_MISO: J2.3 R153.2 ; port DCA_LP_SPI_MISO
DCA_LP_SPI_MOSI: J2.2 R145.2 ; port DCA_LP_SPI_MOSI
I2C_SCL: J1.1 R97.1 R154.1 ; port I2C_SCL
I2C_SDA: J1.2 R98.1 R163.1 ; port I2C_SDA
MCU_SOP0: R164.1 ; port MCU_SOP0
MCU_SOP1: R155.1 ; port MCU_SOP1
nERROR_LED_WD_TP: R100.1 ; port nERROR_LED_WD_TP
PGOOD: R83.2 ; port PGOOD
PMIC_CLKOUT_LIN_PHY_TX_SOP1: R85.2 ; port PMIC_CLKOUT_LIN_PHY_TX_SOP1
RADAR_NRST_2: R144.2 ; port RADAR_NRST_2
USER_LED_SW_GPIO_0: R149.1 ; port USER_LED_SW_GPIO_0
XDS_TDO: R84.2 ; port XDS_TDO
XDS_UARTA_RX: R118.1 R147.1 ; port XDS_UARTA_RX
XDS_UARTA_TX: R77.1 R143.1 ; port XDS_UARTA_TX
NetJ8_5: J8.5 R35.2 R77.2
NetJ8_7: J8.7 R36.2 R118.2
NetJ8_13: J8.13 R146.2
NetJ8_14: J8.14 R83.1
NetJ8_15: J8.15 R149.2
NetJ8_17: J8.17 R154.2
NetJ8_18: J8.18 R84.1
NetJ8_19: J8.19 R163.2
NetJ8_20: J8.20 R85.1
NetJ9_1: J9.1 R100.2
NetJ9_6: J9.6 R140.1
NetJ9_9: J9.9 R143.2
NetJ9_10: J9.10 R144.1
NetJ9_12: J9.12 R145.1
NetJ9_13: J9.13 R147.2
NetJ9_14: J9.14 R153.1
NetJ9_16: J9.16 R133.1
NetJ9_17: J9.17 R155.2
NetJ9_19: J9.19 R164.2

Not connected (* = marked no-connect by the designer): J8 3* 6* 8* 9* 10* 11* 12* 16*; J9 3* 4* 5* 7* 8* 11* 15* 18* 20*

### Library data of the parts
C76 C77 = CMP-0064967-2: as C92 on sheet PROC117B_DCA1000_Connector_Reset
J1 = CMP-0054795-1: Header, 2.54 mm, 3x1, Gold, R/A, TH; Manufacturer: Wurth Elektronik; CNHeader: TRUE; Shrouded: N; Gender: Male; Row_Count: 1; Pitch_mm: 2.54; CT: FALSE
J2 = CMP-0054584-1: Header, 2.54 mm, 7x1, Gold, TH; Manufacturer: Sullins Connector Solutions; CNHeader: TRUE; Current_A: 3A; Shrouded: N; Gender: Male; Voltage_V: 1.8kV; Row_Count: 1; Pitch_mm: 2.54; CT: FALSE; Cert_UL: Y
J8 J9 = CMP-0078182-1: Receptacle, 2.54mm, 10x2, Gold with Tin tail, SMT; Manufacturer: Samtec; Pitch_mm: 2.54; Gender: Female; Cert_CSA: Y; Voltage_V: 405V; Current_A: 5.2A; Row_Count: 2; CompType: Socket Strip
R35 R36 R77 R83-R85 R100 R118 R133 R140 R143-R147 R149 R153-R155 R163 R164 = CMP-0027008-4: as R69 on sheet PROC117B_CAN_LIN_PHY_Interface
R87 R132 = CMP-0025884-3: as R31 on sheet PROC117B_CAN_LIN_PHY_Interface
R95 R96 R99 = CMP-0025950-3: RES, 100 k, 1%, 0.063 W, AEC-Q200 Grade 0, 0402; Manufacturer: Vishay-Dale; Power_W: 63mW; TempCo: 100 ppm/C; Value: 100k; EIA_Code: E96; SizeX_mm: 1; SizeY_mm: 0.5; SizeZ_mm: 0.6; Value2: 0.063W; AEC Qualified: Y; VDC_V: 50V; AEC Category: Q200; AEC Grade: 0
R97 R98 = CMP-0025958-3: as R17 on sheet PROC117B_CAN_LIN_PHY_Interface

## Sheet PROC117B_EVM_Hardware.SchDoc: HARDWARE
size 431 x 279 mm; Date: Not shown in title block; ApprovedBy: Not shown in title block; CheckedBy: Not shown in title block; Author: Not shown in title block; CompanyName: Not shown in title block; DrawnBy: Mistral; Engineer: Not shown in title block; Organization: Not shown in title block; Address1: Not shown in title block; Address2: Not shown in title block; Address3: Not shown in title block; Address4: Not shown in title block; DocumentNumber: 16; Revision: Use project parameter SCH_Rev; SheetNumber: 16; SheetTotal: 16; PageSetup: Record=PageOptions¦CenterHorizontal=True¦CenterVertical=True¦PrintScale=1.00¦XCorrection=1.00¦YCorrection=1.00¦PrintKind=0¦BorderSize=5000000¦LeftOffset=0¦BottomOffset=0¦Orientation=2¦PaperLength=1000¦PaperWidth=1000¦Scale=100¦PaperSource=15¦PrintQuality=600¦MediaType=1¦DitherType=10¦PaperKind=Letter¦PrintScaleMode=1
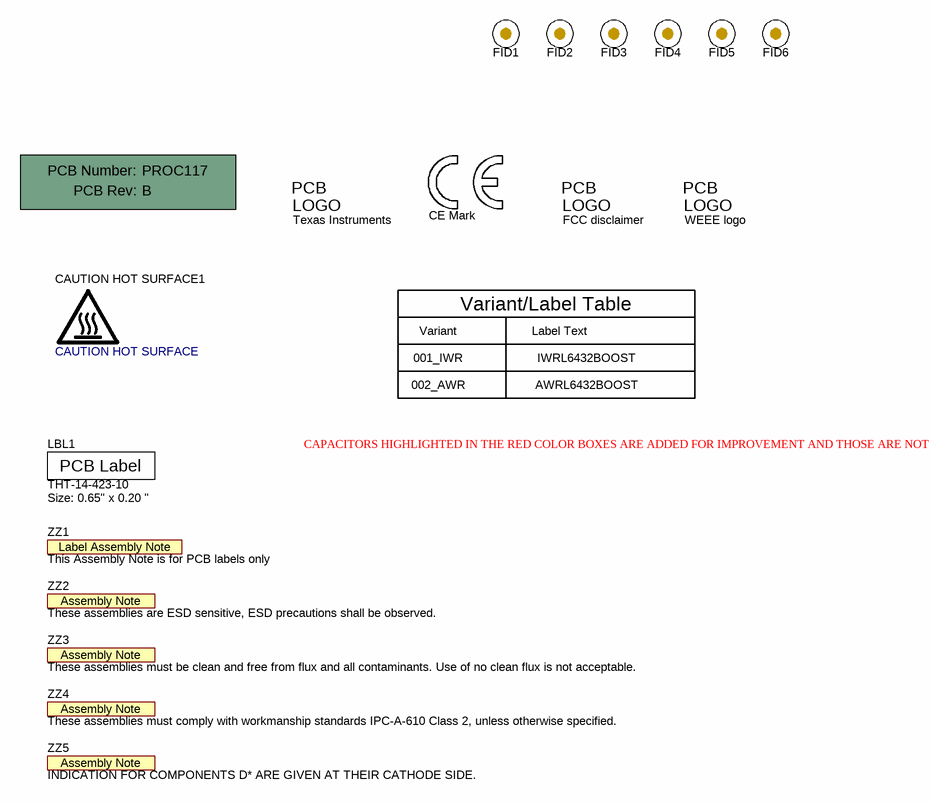
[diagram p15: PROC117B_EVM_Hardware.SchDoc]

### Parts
!PCB  Printed Circuit Board  (value not drawn)  (mechanical)
CAUTION_HOT_SURFACE1  CAUTION HOT SURFACE  [IEC_HotSurface_Small]  (no BOM)
FID1  Fiducial  [Fiducial10-20]  (value not drawn)
FID2  Fiducial  [Fiducial10-20]  (value not drawn)
FID3  Fiducial  [Fiducial10-20]  (value not drawn)
FID4  Fiducial  [Fiducial10-20]  (value not drawn)
FID5  Fiducial  [Fiducial10-20]  (value not drawn)
FID6  Fiducial  [Fiducial10-20]  (value not drawn)
LBL1  THT-14-423-10  Note: Size: 0.65" x 0.20 "  [Label_650x200]
Logo1  Texas Instruments  [TI_Stacked_Overlay_Small]  (no BOM)
Logo2  CE Mark  [CE_Mark_5mm]  (no BOM)
Logo3  FCC disclaimer  [FCC_disclaimer]  (no BOM)
Logo4  WEEE logo  [WEEE_Minimum]  (no BOM)
ZZ1  This Assembly Note is for PCB labels only  [AssemblyNoteLabel]  (no BOM)
ZZ2  These assemblies are ESD sensitive, ESD precautions shall be observed.  [AssemblyNote]  (no BOM)
ZZ3  These assemblies must be clean and free from flux and all contaminants. Use of no clean flux is not acceptable.  [AssemblyNote]  (no BOM)
ZZ4  These assemblies must comply with workmanship standards IPC-A-610 Class 2, unless otherwise specified.  [AssemblyNote]  (no BOM)
ZZ5  INDICATION FOR COMPONENTS D* ARE GIVEN AT THEIR CATHODE SIDE.  [AssemblyNote]  (no BOM)

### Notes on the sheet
- Variant
- 001_IWR
- Variant/Label Table
- Label Text
- IWRL6432BOOST
- 002_AWR
- AWRL6432BOOST
- CAPACITORS HIGHLIGHTED IN THE RED COLOR BOXES ARE ADDED FOR IMPROVEMENT AND THOSE ARE NOT MANDITORY.

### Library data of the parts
!PCB = CMP-0003618-2: Manufacturer: Any; PartNumber: PROC117
CAUTION_HOT_SURFACE1 = CMP-0074837-2: IEC 61010-1 Hot Surface Warning; Manufacturer: Texas Instruments; SymbolCreator: a0412235; AEC Category: Q200; CompType: IC
FID1-FID6 = CMP-0077181-1: Fiducial mark.  There is nothing to buy or mount.
LBL1 = CMP-0003625-1: Thermal Transfer Printable Labels, 0.650" W x 0.200" H - 10,000 per roll; Manufacturer: Brady; CompType: Label
Logo1 = CMP-0074838-1: Texas Instrument Corporate Signature; SymbolCreator: a0412235; Lib Reference: TI_Logo; Library Reference: Logo
Logo2 = CMP-0074844-1: SymbolCreator: a0412235
Logo3 = CMP-0074847-1: FCC_disclaimer; Library Reference: Logo
Logo4 = CMP-0074769-1
ZZ1 = CMP-0003616-3
ZZ2 = CMP-0077236-1
ZZ3 = CMP-0077237-1
ZZ4 ZZ5 = CMP-0077238-1

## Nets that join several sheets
5V_IN: PROC117B_USB_PWR_DC_Jack_Switch (7 pins), PROC117B_DC_Regulators (18 pins), PROC117B_XDS110_Interface_1A (R9.1), PROC117B_CAN_LIN_PHY_Interface (J4.1 R31.1 R69.2), PROC117B_DCA1000_Connector_Reset (R30.1 R141.1), PROC117B_LP_BP_Connector (R87.2)
CB_REG_1V2: PROC117B_Decoupling_caps (C64.2 R183.1), PROC117B_Temp_Current_sensors_EPROM (R193.2 U8.9)
CB_REG_1V8: PROC117B_Decoupling_caps (C1.2 R182.1), PROC117B_Temp_Current_sensors_EPROM (R192.2 U6.9)
CB_REG_RF_1V2: PROC117B_Decoupling_caps (C103.2 R92.1), PROC117B_Temp_Current_sensors_EPROM (R134.2 U25.9)
GND: PROC117B_USB_PWR_DC_Jack_Switch (31 pins), PROC117B_DC_Regulators (36 pins), PROC117B_xWRL6432_Chip (49 pins), PROC117B_Decoupling_caps (42 pins), PROC117B_Temp_Current_sensors_EPROM (23 pins), PROC117B_QSPI_Flash_LVDS_Driver (16 pins), PROC117B_Analog_Mux_SOP_Ctrl (17 pins), PROC117B_XDS110_Interface_1A (19 pins), PROC117B_XDS110_Interface_1B (21 pins), PROC117B_CAN_LIN_PHY_Interface (10 pins), PROC117B_DCA1000_Connector_Reset (25 pins), PROC117B_LP_BP_Connector (6 pins)
RADAR_1P2_RF: PROC117B_xWRL6432_Chip (U1.L4 U1.M4), PROC117B_Decoupling_caps (8 pins)
RADAR_1V2: PROC117B_xWRL6432_Chip (8 pins), PROC117B_Decoupling_caps (11 pins)
RADAR_1V4_APLL: PROC117B_xWRL6432_Chip (U1.G5), PROC117B_Decoupling_caps (C22.2)
RADAR_1V4_SYNTH: PROC117B_xWRL6432_Chip (U1.D3), PROC117B_Decoupling_caps (C18.2)
RADAR_1V8: PROC117B_xWRL6432_Chip (9 pins), PROC117B_Decoupling_caps (14 pins)
RADAR_1V_RF_OUT: PROC117B_xWRL6432_Chip (U1.L3 U1.M3), PROC117B_Decoupling_caps (C9.2 C19.2 C23.1)
RADAR_3V3: PROC117B_xWRL6432_Chip (10 pins), PROC117B_Decoupling_caps (C16.2 C17.2 C21.2), PROC117B_Temp_Current_sensors_EPROM (R200.2 U7.9), PROC117B_DCA1000_Connector_Reset (R64.2 R65.1)
RADAR_VBGAP: PROC117B_xWRL6432_Chip (U1.H5), PROC117B_Decoupling_caps (C6.1)
REG_1V2: PROC117B_DC_Regulators (C61.2 L5.2), PROC117B_xWRL6432_Chip (R86.2), PROC117B_Temp_Current_sensors_EPROM (R193.1 U8.8 U8.10)
REG_1V8: PROC117B_DC_Regulators (C68.2 L6.2), PROC117B_xWRL6432_Chip (R67.2), PROC117B_Temp_Current_sensors_EPROM (R192.1 U6.8 U6.10)
REG_RF_1V2: PROC117B_DC_Regulators (C79.2 L1.2), PROC117B_Temp_Current_sensors_EPROM (R134.1 U25.8 U25.10)
VCC_3V3: PROC117B_USB_PWR_DC_Jack_Switch (R172.2), PROC117B_DC_Regulators (L11.2 R198.2 TP9.1), PROC117B_Temp_Current_sensors_EPROM (30 pins), PROC117B_QSPI_Flash_LVDS_Driver (13 pins), PROC117B_Analog_Mux_SOP_Ctrl (13 pins), PROC117B_CAN_LIN_PHY_Interface (C38.2 R17.2 R22.2 U5.5), PROC117B_DCA1000_Connector_Reset (7 pins), PROC117B_LP_BP_Connector (7 pins)
VCC_XDS_3V3: PROC117B_XDS110_Interface_1A (11 pins), PROC117B_XDS110_Interface_1B (20 pins)
VDDC_1: PROC117B_XDS110_Interface_1A (C124.2 C125.2 C126.2 C127.1), PROC117B_XDS110_Interface_1B (U21.87 U21.115)
XDSET_1_VBUS: PROC117B_USB_PWR_DC_Jack_Switch (R1.1 U9.6), PROC117B_XDS110_Interface_1A (R236.2), PROC117B_XDS110_Interface_1B (R169.2)
CAN_PHY_RX: PROC117B_Analog_Mux_SOP_Ctrl (U12.5), PROC117B_CAN_LIN_PHY_Interface (R80.1)
CAN_PHY_TX: PROC117B_Analog_Mux_SOP_Ctrl (U12.9), PROC117B_CAN_LIN_PHY_Interface (R78.1)
CAN_STB_CTRL: PROC117B_Analog_Mux_SOP_Ctrl (S4.2), PROC117B_CAN_LIN_PHY_Interface (R3.1)
DCA_LP_HOST_INTR_1: PROC117B_xWRL6432_Chip (R23.2 R152.1), PROC117B_Analog_Mux_SOP_Ctrl (U24.12), PROC117B_DCA1000_Connector_Reset (R42.2), PROC117B_LP_BP_Connector (J2.6 R133.2)
DCA_LP_HOST_INTR_GPIO_0_LED: PROC117B_xWRL6432_Chip (U1.J10), PROC117B_Analog_Mux_SOP_Ctrl (U24.10)
DCA_LP_RS232_RX: PROC117B_Analog_Mux_SOP_Ctrl (U12.3), PROC117B_DCA1000_Connector_Reset (R61.1), PROC117B_LP_BP_Connector (R36.1 R96.1)
DCA_LP_RS232_TX: PROC117B_Analog_Mux_SOP_Ctrl (U12.15), PROC117B_DCA1000_Connector_Reset (R62.1), PROC117B_LP_BP_Connector (R35.1 R95.1)
DCA_LP_SPI_CLK: PROC117B_Analog_Mux_SOP_Ctrl (U24.16), PROC117B_DCA1000_Connector_Reset (R41.1), PROC117B_LP_BP_Connector (J2.5 R146.1)
DCA_LP_SPI_CLK_I2C_SCL: PROC117B_xWRL6432_Chip (R75.1 U1.D10), PROC117B_Analog_Mux_SOP_Ctrl (U24.2)
DCA_LP_SPI_CS: PROC117B_Analog_Mux_SOP_Ctrl (U24.3), PROC117B_DCA1000_Connector_Reset (R39.1), PROC117B_LP_BP_Connector (J2.4 R99.1 R140.2)
DCA_LP_SPI_CS_I2C_SDA: PROC117B_xWRL6432_Chip (R4.1 U1.D11), PROC117B_Analog_Mux_SOP_Ctrl (U24.5)
DCA_LP_SPI_MISO: PROC117B_Analog_Mux_SOP_Ctrl (U24.9), PROC117B_DCA1000_Connector_Reset (R53.2), PROC117B_LP_BP_Connector (J2.3 R153.2)
DCA_LP_SPI_MISO_REG_MODE: PROC117B_xWRL6432_Chip (U1.C11), PROC117B_Analog_Mux_SOP_Ctrl (U24.7)
DCA_LP_SPI_MOSI: PROC117B_xWRL6432_Chip (U1.B12), PROC117B_DCA1000_Connector_Reset (R52.1), PROC117B_LP_BP_Connector (J2.2 R145.2)
DCA_TCK: PROC117B_Analog_Mux_SOP_Ctrl (U4.16), PROC117B_DCA1000_Connector_Reset (R38.2)
DCA_TDI: PROC117B_Analog_Mux_SOP_Ctrl (U4.3), PROC117B_DCA1000_Connector_Reset (R37.1)
DCA_TDO: PROC117B_Analog_Mux_SOP_Ctrl (U4.9), PROC117B_DCA1000_Connector_Reset (R34.2)
DCA_TMS: PROC117B_Analog_Mux_SOP_Ctrl (U4.12), PROC117B_DCA1000_Connector_Reset (R40.2)
I2C_SCL: PROC117B_Temp_Current_sensors_EPROM (6 pins), PROC117B_Analog_Mux_SOP_Ctrl (U24.1), PROC117B_XDS110_Interface_1B (R199.1 S5.2), PROC117B_DCA1000_Connector_Reset (R60.1), PROC117B_LP_BP_Connector (J1.1 R97.1 R154.1)
I2C_SDA: PROC117B_Temp_Current_sensors_EPROM (6 pins), PROC117B_Analog_Mux_SOP_Ctrl (U24.4), PROC117B_XDS110_Interface_1B (R197.1 S5.1), PROC117B_DCA1000_Connector_Reset (R59.1), PROC117B_LP_BP_Connector (J1.2 R98.1 R163.1)
LIN_PHY_EN_CTRL: PROC117B_Analog_Mux_SOP_Ctrl (S4.3), PROC117B_CAN_LIN_PHY_Interface (R88.1)
LIN_PHY_RX: PROC117B_QSPI_Flash_LVDS_Driver (U15.2), PROC117B_CAN_LIN_PHY_Interface (R18.1 R22.1)
LVDS_CLK_RTC_CLKIN_TP: PROC117B_xWRL6432_Chip (U1.L11), PROC117B_QSPI_Flash_LVDS_Driver (U15.10)
LVDS_D0_LIN_PHY_RX: PROC117B_xWRL6432_Chip (U1.H10), PROC117B_QSPI_Flash_LVDS_Driver (U15.4)
LVDS_D1_XDS_UARTA_RX_CAN_RX: PROC117B_xWRL6432_Chip (U1.J11), PROC117B_QSPI_Flash_LVDS_Driver (U15.6)
LVDS_D2_XDS_UARTA_TX_CAN_TX: PROC117B_xWRL6432_Chip (U1.L12), PROC117B_QSPI_Flash_LVDS_Driver (U15.7)
LVDS_D3_nERROR_LED_WD_TP: PROC117B_xWRL6432_Chip (U1.K11), PROC117B_QSPI_Flash_LVDS_Driver (U15.9)
LVDS_FRCLK_HOST_CLK_TP: PROC117B_xWRL6432_Chip (U1.M10), PROC117B_QSPI_Flash_LVDS_Driver (U15.12)
MCU_SOP0: PROC117B_Analog_Mux_SOP_Ctrl (R13.1), PROC117B_LP_BP_Connector (R164.1)
MCU_SOP1: PROC117B_Analog_Mux_SOP_Ctrl (R16.1), PROC117B_LP_BP_Connector (R155.1)
MUX_CTRL_LVDS_UART_CAN_TP: PROC117B_QSPI_Flash_LVDS_Driver (R90.2 U15.14 U15.24), PROC117B_Analog_Mux_SOP_Ctrl (S1.3)
nERROR_LED_WD_TP: PROC117B_QSPI_Flash_LVDS_Driver (TP2.1 U15.21), PROC117B_DCA1000_Connector_Reset (D9.2 R65.2), PROC117B_LP_BP_Connector (R100.1)
PGOOD: PROC117B_USB_PWR_DC_Jack_Switch (R179.1), PROC117B_DC_Regulators (R198.1 R201.2), PROC117B_XDS110_Interface_1A (R241.1), PROC117B_DCA1000_Connector_Reset (R58.1), PROC117B_LP_BP_Connector (R83.2)
PMIC_CLKOUT_LIN_PHY_TX_SOP1: PROC117B_xWRL6432_Chip (U1.H11), PROC117B_Analog_Mux_SOP_Ctrl (R15.1 R206.1), PROC117B_CAN_LIN_PHY_Interface (R19.1), PROC117B_LP_BP_Connector (R85.2)
QSPI_CS: PROC117B_xWRL6432_Chip (U1.A10), PROC117B_QSPI_Flash_LVDS_Driver (R50.2 U2.1)
QSPI_D0: PROC117B_xWRL6432_Chip (U1.B11), PROC117B_QSPI_Flash_LVDS_Driver (R45.2)
QSPI_D1: PROC117B_xWRL6432_Chip (U1.B8), PROC117B_QSPI_Flash_LVDS_Driver (R46.1)
QSPI_D2: PROC117B_xWRL6432_Chip (U1.B10), PROC117B_QSPI_Flash_LVDS_Driver (R44.1 R47.1)
QSPI_D3: PROC117B_xWRL6432_Chip (U1.B9), PROC117B_QSPI_Flash_LVDS_Driver (R49.1 R51.2)
QSPI_SCLK: PROC117B_xWRL6432_Chip (U1.A11), PROC117B_QSPI_Flash_LVDS_Driver (R48.2)
RADAR_LVDS_0M: PROC117B_QSPI_Flash_LVDS_Driver (U10.3), PROC117B_DCA1000_Connector_Reset (R230.2)
RADAR_LVDS_0P: PROC117B_QSPI_Flash_LVDS_Driver (U10.2), PROC117B_DCA1000_Connector_Reset (R229.2)
RADAR_LVDS_1M: PROC117B_QSPI_Flash_LVDS_Driver (U10.5), PROC117B_DCA1000_Connector_Reset (R228.2)
RADAR_LVDS_1P: PROC117B_QSPI_Flash_LVDS_Driver (U10.6), PROC117B_DCA1000_Connector_Reset (R227.2)
RADAR_LVDS_2M: PROC117B_QSPI_Flash_LVDS_Driver (U10.11), PROC117B_DCA1000_Connector_Reset (R224.2)
RADAR_LVDS_2P: PROC117B_QSPI_Flash_LVDS_Driver (U10.10), PROC117B_DCA1000_Connector_Reset (R223.2)
RADAR_LVDS_3M: PROC117B_QSPI_Flash_LVDS_Driver (U10.13), PROC117B_DCA1000_Connector_Reset (R222.2)
RADAR_LVDS_3P: PROC117B_QSPI_Flash_LVDS_Driver (U10.14), PROC117B_DCA1000_Connector_Reset (R221.2)
RADAR_LVDS_CLKM: PROC117B_QSPI_Flash_LVDS_Driver (U14.3), PROC117B_DCA1000_Connector_Reset (R226.2)
RADAR_LVDS_CLKP: PROC117B_QSPI_Flash_LVDS_Driver (U14.2), PROC117B_DCA1000_Connector_Reset (R225.2)
RADAR_LVDS_FRCLKM: PROC117B_QSPI_Flash_LVDS_Driver (U14.5), PROC117B_DCA1000_Connector_Reset (R220.2)
RADAR_LVDS_FRCLKP: PROC117B_QSPI_Flash_LVDS_Driver (U14.6), PROC117B_DCA1000_Connector_Reset (R219.2)
RADAR_NRST: PROC117B_DC_Regulators (R176.1), PROC117B_xWRL6432_Chip (R20.1 U1.L10), PROC117B_DCA1000_Connector_Reset (R171.1 U17.4)
RADAR_NRST_2: PROC117B_DCA1000_Connector_Reset (5 pins), PROC117B_LP_BP_Connector (R144.2)
REG_MODE_SELECT: PROC117B_DC_Regulators (R173.2), PROC117B_Analog_Mux_SOP_Ctrl (U24.8)
USER_LED_SW_GPIO_0: PROC117B_Analog_Mux_SOP_Ctrl (U24.11), PROC117B_DCA1000_Connector_Reset (R66.1 R214.2), PROC117B_LP_BP_Connector (R149.1)
VBUS_1_DETECT: PROC117B_XDS110_Interface_1A (C118.2 R236.1 R239.2), PROC117B_XDS110_Interface_1B (U21.1)
XDS_DCA_LP_RS232_RX: PROC117B_xWRL6432_Chip (R74.1 U1.F11), PROC117B_Analog_Mux_SOP_Ctrl (U12.2)
XDS_DCA_LP_RS232_TX: PROC117B_xWRL6432_Chip (R73.1 U1.E10), PROC117B_Analog_Mux_SOP_Ctrl (U12.14)
XDS_DCA_TCK: PROC117B_xWRL6432_Chip (U1.C12), PROC117B_Analog_Mux_SOP_Ctrl (U4.2)
XDS_DCA_TDI: PROC117B_xWRL6432_Chip (U1.G11), PROC117B_Analog_Mux_SOP_Ctrl (U4.5)
XDS_DCA_TDO_SOP0: PROC117B_xWRL6432_Chip (R93.1), PROC117B_Analog_Mux_SOP_Ctrl (R156.2 U4.7)
XDS_DCA_TMS: PROC117B_xWRL6432_Chip (U1.E12), PROC117B_Analog_Mux_SOP_Ctrl (U4.10)
XDS_NRST: PROC117B_XDS110_Interface_1B (R126.2), PROC117B_DCA1000_Connector_Reset (R138.1 U17.3)
XDS_RS232_RX: PROC117B_Analog_Mux_SOP_Ctrl (U12.1), PROC117B_XDS110_Interface_1B (R24.2 R188.1)
XDS_RS232_TX: PROC117B_Analog_Mux_SOP_Ctrl (U12.13), PROC117B_XDS110_Interface_1B (R26.2 R181.1)
XDS_TCK: PROC117B_Analog_Mux_SOP_Ctrl (U4.1), PROC117B_XDS110_Interface_1B (R122.2)
XDS_TDI: PROC117B_Analog_Mux_SOP_Ctrl (U4.4), PROC117B_XDS110_Interface_1B (R125.2)
XDS_TDO: PROC117B_Analog_Mux_SOP_Ctrl (U4.8), PROC117B_XDS110_Interface_1B (U21.37), PROC117B_LP_BP_Connector (R84.2)
XDS_TMS: PROC117B_Analog_Mux_SOP_Ctrl (U4.11), PROC117B_XDS110_Interface_1B (R124.2)
XDS_UARTA_RX: PROC117B_xWRL6432_Chip (R82.1), PROC117B_Analog_Mux_SOP_Ctrl (R127.2 U12.7), PROC117B_XDS110_Interface_1B (R24.1), PROC117B_LP_BP_Connector (R118.1 R147.1)
XDS_UARTA_RX_CAN_RX: PROC117B_QSPI_Flash_LVDS_Driver (U15.1), PROC117B_Analog_Mux_SOP_Ctrl (R127.1 U12.6)
XDS_UARTA_TX: PROC117B_xWRL6432_Chip (R81.1), PROC117B_Analog_Mux_SOP_Ctrl (R128.2 U12.11), PROC117B_XDS110_Interface_1B (R26.1 R190.1), PROC117B_LP_BP_Connector (R77.1 R143.1)
XDS_UARTA_TX_CAN_TX: PROC117B_QSPI_Flash_LVDS_Driver (U15.23), PROC117B_Analog_Mux_SOP_Ctrl (R128.1 U12.10)
XDSET_1_DM: PROC117B_USB_PWR_DC_Jack_Switch (J5.2 U9.4), PROC117B_XDS110_Interface_1B (U21.93)
XDSET_1_DP: PROC117B_USB_PWR_DC_Jack_Switch (J5.3 U9.5), PROC117B_XDS110_Interface_1B (U21.94)
XDSET_1_ID: PROC117B_USB_PWR_DC_Jack_Switch (J5.4 U9.2), PROC117B_XDS110_Interface_1B (R170.2)

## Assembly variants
001_IWR: not fitted C87 C107 C121 C122 C123 C130 C131 C132 D8 FB2 FID1 FID2 FID3 FID4 FID5 FID6 J4 R2 R14 R15 R17 R18 R19 R21 R22 R24 R26 R30 R31 R32 R57 R59 R60 R65 R77 R84 R85 R87 R88 R97 R98 R107 R113 R114 R116 R118 R127 R128 R132 R135 R147 R150 R152 R157 R161 R176 R197 R199 TP10 U23
002_AWR: not fitted C87 C107 C121 C122 C130 C131 FB2 FID1 FID2 FID3 FID4 FID5 FID6 R2 R14 R15 R24 R26 R30 R32 R57 R59 R60 R65 R77 R84 R85 R87 R97 R98 R107 R113 R114 R116 R118 R127 R128 R132 R135 R147 R150 R152 R157 R161 R176 R197 R199 TP10; alternate parts U1 -> CMP-0095271-2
